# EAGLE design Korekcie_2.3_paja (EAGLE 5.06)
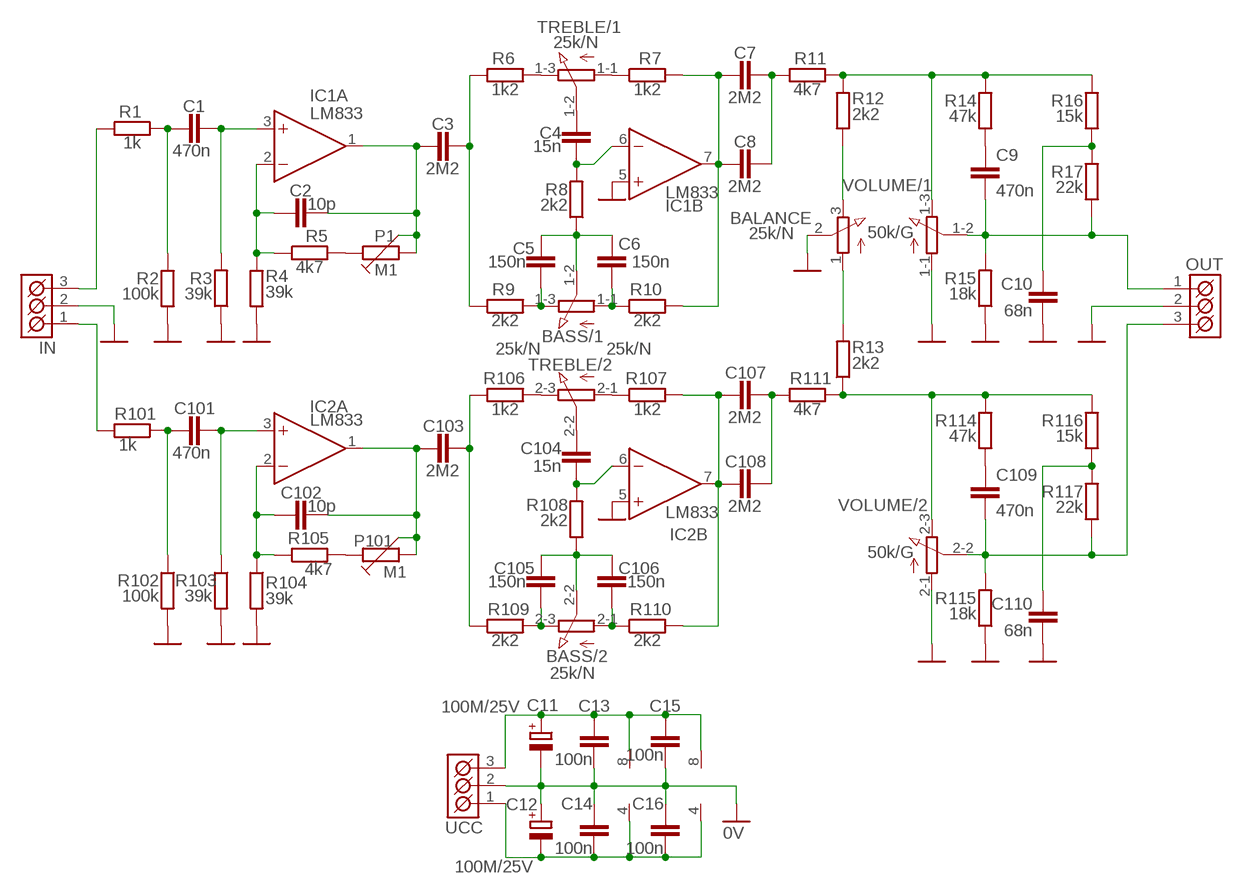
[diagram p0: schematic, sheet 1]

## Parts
BALANCE  25k/N  3RP/1610N  [3RP/1610N]
BASS  25k/N  3RP/1610G  [3RP/1610G]
C1  470n  C-EU050-055X075  [C050-055X075]
C2  10p  C-EU025-024X044  [C025-024X044]
C3  2M2  C-EU050-055X075  [C050-055X075]
C4  15n  C-EU050-025X075  [C050-025X075]
C5  150n  C-EU050-025X075  [C050-025X075]
C6  150n  C-EU050-025X075  [C050-025X075]
C7  2M2  C-EU050-055X075  [C050-055X075]
C8  2M2  C-EU050-055X075  [C050-055X075]
C9  470n  C-EU050-055X075  [C050-055X075]
C10  68n  C-EU050-025X075  [C050-025X075]
C11  100M/25V  CPOL-EUE3.5-8  [E3,5-8]
C12  100M/25V  CPOL-EUE3.5-8  [E3,5-8]
C13  100n  C-EU050-025X075  [C050-025X075]
C14  100n  C-EU050-025X075  [C050-025X075]
C15  100n  C-EU050-025X075  [C050-025X075]
C16  100n  C-EU050-025X075  [C050-025X075]
C101  470n  C-EU050-055X075  [C050-055X075]
C102  10p  C-EU025-024X044  [C025-024X044]
C103  2M2  C-EU050-055X075  [C050-055X075]
C104  15n  C-EU050-025X075  [C050-025X075]
C105  150n  C-EU050-025X075  [C050-025X075]
C106  150n  C-EU050-025X075  [C050-025X075]
C107  2M2  C-EU050-055X075  [C050-055X075]
C108  2M2  C-EU050-055X075  [C050-055X075]
C109  470n  C-EU050-055X075  [C050-055X075]
C110  68n  C-EU050-025X075  [C050-025X075]
IC1  LM833  [DIL-08]
IC2  LM833  [DIL-08]
IN  ARK500/3  [ARK500/3]
OUT  ARK500/3  [ARK500/3]
P1  M1  TRIMRPT10V  [PT10V]
P101  M1  TRIMRPT10V  [PT10V]
R1  1k  R-EU_0204/7  [0204/7]
R2  100k  R-EU_0204/7  [0204/7]
R3  39k  R-EU_0204/7  [0204/7]
R4  39k  R-EU_0204/7  [0204/7]
R5  4k7  R-EU_0204/7  [0204/7]
R6  1k2  R-EU_0204/7  [0204/7]
R7  1k2  R-EU_0207/12  [0207/12]
R8  2k2  R-EU_0204/7  [0204/7]
R9  2k2  R-EU_0204/7  [0204/7]
R10  2k2  R-EU_0204/7  [0204/7]
R11  4k7  R-EU_0204/7  [0204/7]
R12  2k2  R-EU_0204/7  [0204/7]
R13  2k2  R-EU_0204/7  [0204/7]
R14  47k  R-EU_0204/7  [0204/7]
R15  18k  R-EU_0204/7  [0204/7]
R16  15k  R-EU_0204/7  [0204/7]
R17  22k  R-EU_0204/7  [0204/7]
R101  1k  R-EU_0204/7  [0204/7]
R102  100k  R-EU_0204/7  [0204/7]
R103  39k  R-EU_0204/7  [0204/7]
R104  39k  R-EU_0204/7  [0204/7]
R105  4k7  R-EU_0204/7  [0204/7]
R106  1k2  R-EU_0204/7  [0204/7]
R107  1k2  R-EU_0207/10  [0207/10]
R108  2k2  R-EU_0204/7  [0204/7]
R109  2k2  R-EU_0204/7  [0204/7]
R110  2k2  R-EU_0204/7  [0204/7]
R111  4k7  R-EU_0204/7  [0204/7]
R114  47k  R-EU_0204/7  [0204/7]
R115  18k  R-EU_0204/7  [0204/7]
R116  15k  R-EU_0204/7  [0204/7]
R117  22k  R-EU_0204/7  [0204/7]
TREBLE  25k/N  3RP/1610G  [3RP/1610G]
UCC  ARK500/3  [ARK500/3]
VOLUME  50k/G  3RP/1610G  [3RP/1610G]

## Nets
0V: BALANCE.2(S) C10.1 C11.- C12.+ C13.1 C14.2 C15.1 C16.2 C110.1 IC1.5(B:+IN) IC2.5(B:+IN) IN.2(K2) OUT.2(K2) R2.2 R3.1 R4.2 R15.1 R102.2 R103.2 R104.2 R115.1 UCC.2(K2) VOLUME.1-1(/1:A) VOLUME.2-1(/2:A)
+VCC: C11.+ C13.2 C15.2 IC1.8(P:V+) IC2.8(P:V+) UCC.3(K3)
-VCC: C12.- C14.1 C16.1 IC1.4(P:V-) IC2.4(P:V-) UCC.1(K1)
N$1: C1.2 IC1.3(A:+IN) R3.2
N$2: C2.1 IC1.2(A:-IN) R4.1 R5.1
N$3: P1.1 R5.2
N$4: C2.2 C3.1 IC1.1(A:OUT) P1.2 P1.3
N$5: C1.1 R1.1 R2.1
N$6: C3.2 R6.1 R9.1
N$7: C101.2 IC2.3(A:+IN) R103.1
N$8: C101.1 R101.1 R102.1
N$9: C102.1 IC2.2(A:-IN) R104.1 R105.1
N$10: P101.1 R105.2
N$11: C102.2 C103.1 IC2.1(A:OUT) P101.2 P101.3
N$12: C103.2 R106.1 R109.1
N$13: IN.3(K3) R1.2
N$14: IN.1(K1) R101.2
N$15: BASS.2-3(/2:E) C105.2 R109.2
N$16: C4.2 TREBLE.1-2(/1:S)
N$17: C4.1 IC1.6(B:-IN) R8.2
N$18: BASS.2-1(/2:A) C106.2 R110.1
N$19: BASS.1-3(/1:E) C5.2 R9.2
N$20: BASS.1-2(/1:S) C5.1 C6.2 R8.1
N$21: BASS.1-1(/1:A) C6.1 R10.1
N$22: C7.1 C8.1 IC1.7(B:OUT) R7.2 R10.2
N$23: C7.2 C8.2 R11.1
N$24: R107.1 TREBLE.2-1(/2:A)
N$25: R106.2 TREBLE.2-3(/2:E)
N$26: C104.2 TREBLE.2-2(/2:S)
N$27: C104.1 IC2.6(B:-IN) R108.2
N$28: C107.2 C108.2 IC2.7(B:OUT) R107.2 R110.2
N$29: BASS.2-2(/2:S) C105.1 C106.1 R108.1
N$30: R6.2 TREBLE.1-3(/1:E)
N$31: R7.1 TREBLE.1-1(/1:A)
N$32: C107.1 C108.1 R111.1
N$33: C109.2 OUT.3(K3) R115.2 R117.1 VOLUME.2-2(/2:S)
N$35: BALANCE.1(A) R13.2
N$36: BALANCE.3(E) R12.1
N$37: C9.1 R14.1
N$38: C10.2 R16.1 R17.2
N$39: R11.2 R12.2 R14.2 R16.2 VOLUME.1-3(/1:E)
N$40: C9.2 OUT.1(K1) R15.2 R17.1 VOLUME.1-2(/1:S)
N$41: C110.2 R116.1 R117.2
N$42: C109.1 R114.1
N$43: R13.1 R111.2 R114.2 R116.2 VOLUME.2-3(/2:E)

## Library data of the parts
BALANCE = pot:3RP/1610N: 16mm Potentiometer one level Source: http://www.alphapotentiometers.net/html/16mm_pot_2.html
BASS TREBLE VOLUME = 0 nalimko:3RP/1610G: 16mm Potentiometer two level Source: http://www.alphapotentiometers.net/html/16mm_pot_2.html
C1-C10 C13-C16 C101-C110 = rcl:C-EU: CAPACITOR, European symbol
C11 C12 = rcl:CPOL-EU: POLARIZED CAPACITOR, European symbol
IC1 IC2 = #_GM99:LM833
IN OUT UCC = #PaJa_konektory:ARK500/3: Svorkovnice - roztec 5mm - trojita
P1 P101 = #PaJa_22:TRIMR: Trimr
R1-R17 R101-R111 R114-R117 = rcl:R-EU_: RESISTOR, European symbol

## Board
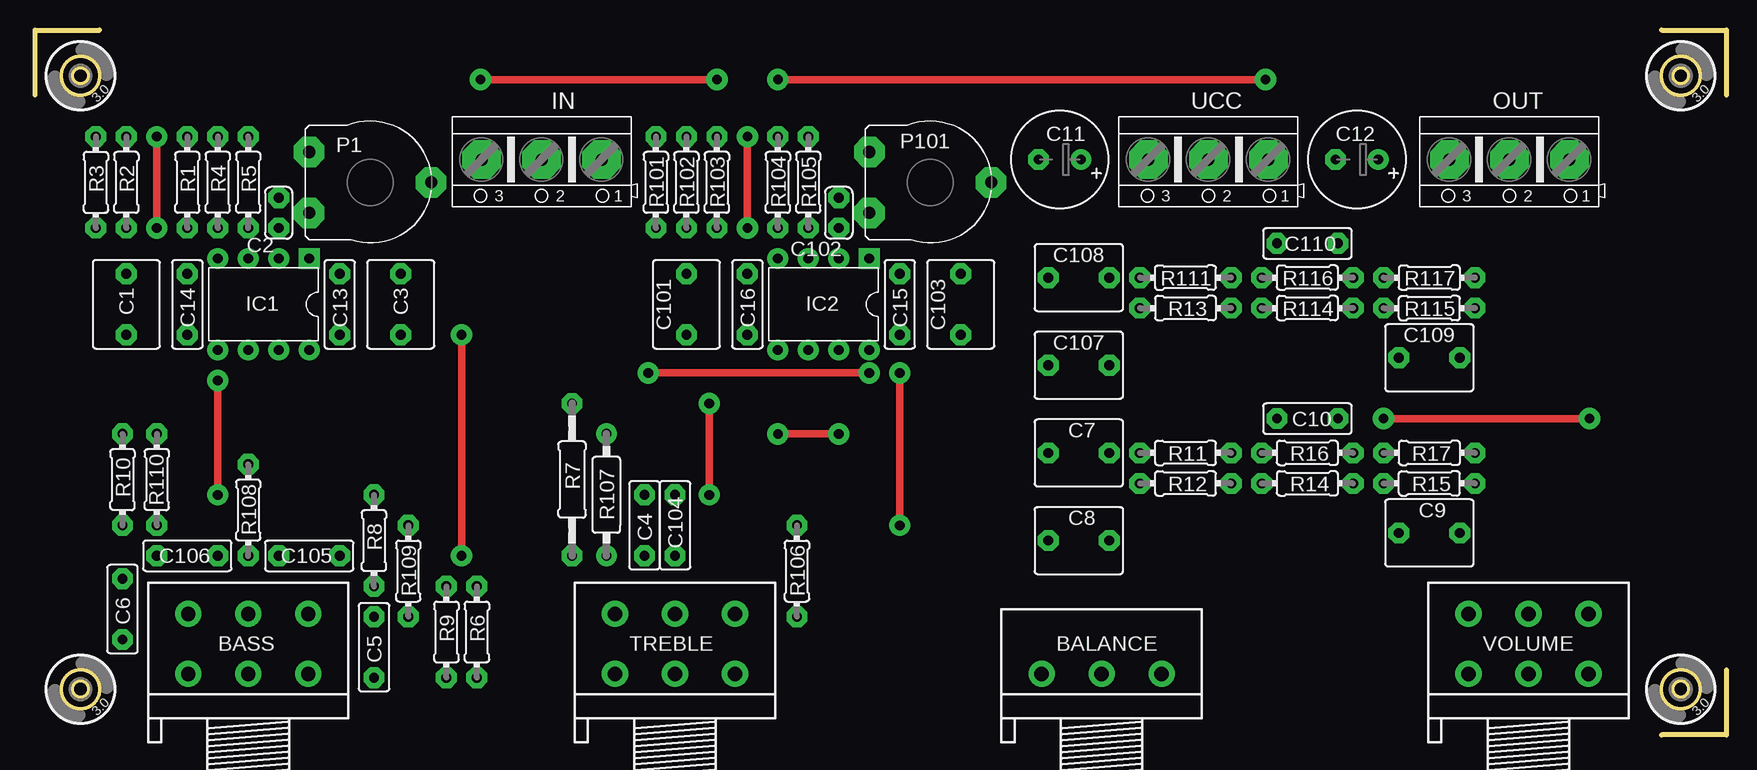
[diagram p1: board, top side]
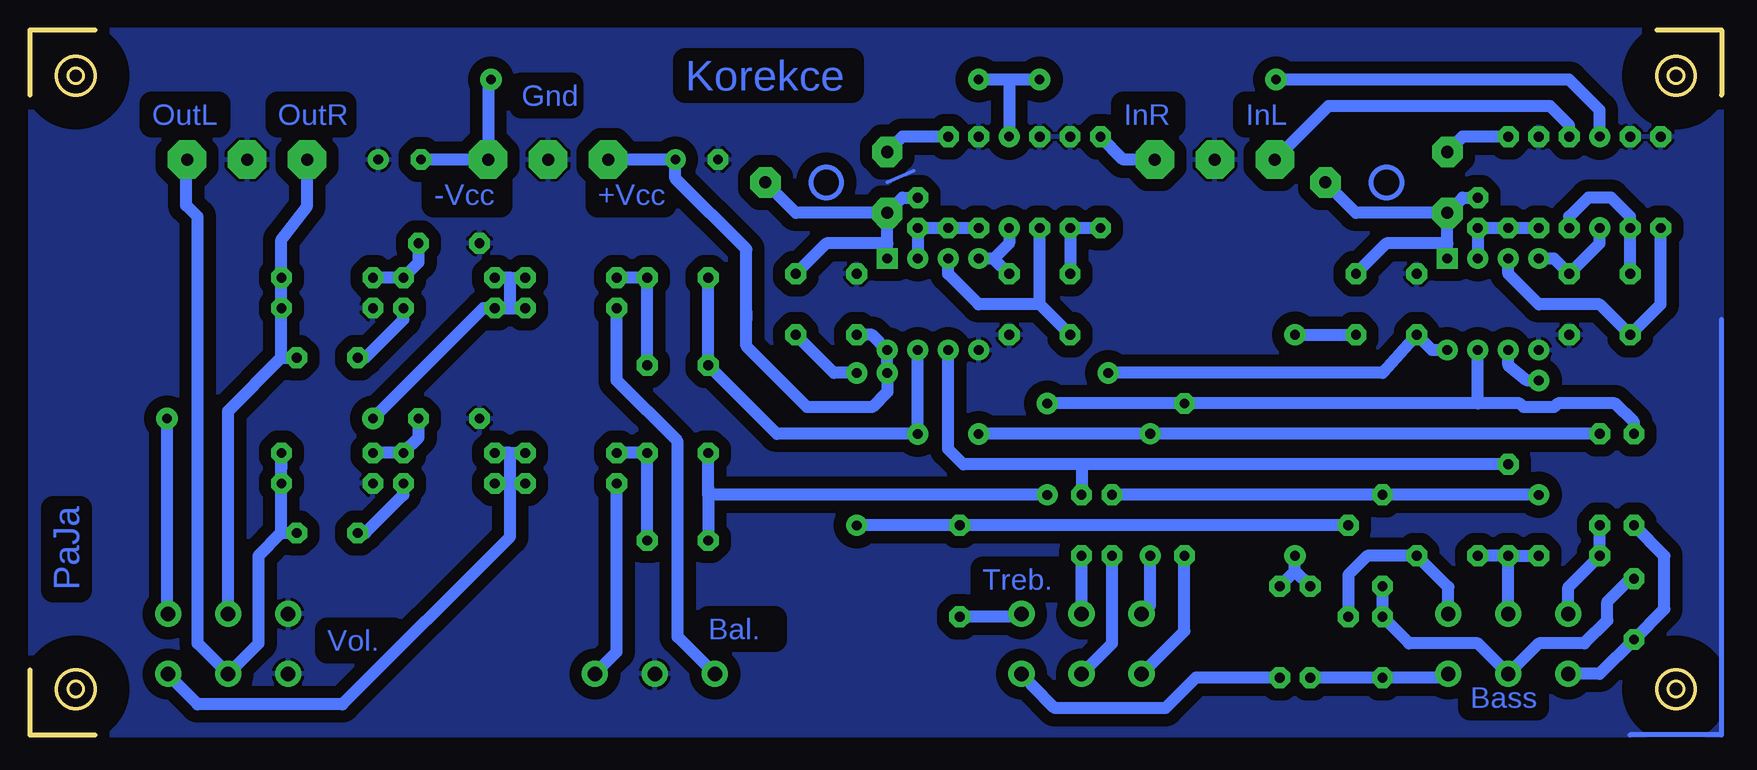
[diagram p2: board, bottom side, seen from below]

Size 140.97 x 58.74 mm. Coordinates in mm from the lower left corner, seen from the top.
Outline: 0,53.34 0,58.74 5.4,58.74
Outline: 135.57,58.74 140.97,58.74 140.97,53.34
Outline: 140.97,5.4 140.97,0 135.57,0
Copper layers (1*16): Top 0.035mm / dielectric 1.5mm / Bottom 0.035mm
Design rules "default *": minimum track width 10mil, minimum drill 24mil, track to track 8mil, track to pad 8mil, pad to pad 8mil, via to via 8mil, smd to smd 8mil, copper to edge 40mil, drill to drill 8mil, minimum pad ring 18mil, minimum via ring 8mil, stop-mask expansion 4mil, vias tented up to drill 0mil, thermal gap 10mil

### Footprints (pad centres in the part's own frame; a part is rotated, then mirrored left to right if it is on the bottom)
3RP/1610N = drill 1.2 pad 2.184 round: 1 -5,0; 2 0,0; 3 5,0
3RP/1610G = drill 1.2 pad 2.184 round: 1-1 -5,0; 1-2 0,0; 1-3 5,0; 2-1 -5,5; 2-2 0,5; 2-3 5,5
C050-055X075 = drill 0.813 octagon: 1 -2.54,0; 2 2.54,0
C025-024X044 = drill 0.813 octagon: 1 -1.27,0; 2 1.27,0
C050-025X075 = drill 0.813 octagon: 1 -2.54,0; 2 2.54,0
E3,5-8 = drill 0.813 pad 1.6 round: + -1.778,0 | drill 0.813 pad 1.6 octagon: - 1.778,0
HOLE_3,0 = hole 3.2: 0,0
DIL-08 = drill 0.813 pad 1.397 square: 1 -3.81,-3.81 | drill 0.813 pad 1.397 round: 2 -1.27,-3.81; 3 1.27,-3.81; 4 3.81,-3.81; 5 3.81,3.81; 6 1.27,3.81; 7 -1.27,3.81; 8 -3.81,3.81
ARK500/3 = drill 1 pad 3.2 octagon: 1 -5,0; 2 0,0; 3 5,0
PT10V = drill 1.016 pad 2.54 octagon: 1 -2.54,-5.08; 2 0,5.08; 3 2.54,-5.08
0204/7 = drill 0.813 octagon: 1 -3.81,0; 2 3.81,0
0207/12 = drill 0.813 octagon: 1 -6.35,0; 2 6.35,0
0207/10 = drill 0.813 round: 1 -5.08,0; 2 5.08,0

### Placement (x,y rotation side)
BALANCE  88.9,5.08 0 top
BASS  17.78,5.08 0 top
C1  7.62,35.88 270 top
C2  20.32,43.5 90 top
C3  30.48,35.88 270 top
C4  50.8,17.46 270 top
C5  28.26,7.3 270 top
C6  7.3,10.48 90 top
C7  87,23.5 0 top
C8  87,16.19 0 top
C9  116.2,16.83 0 top
C10  106.05,26.35 0 top
C11  85.41,47.94 180 top
C12  110.17,47.94 180 top
C13  25.4,35.88 270 top
C14  12.7,35.88 270 top
C15  72.07,35.88 270 top
C16  59.37,35.88 270 top
C101  54.29,35.88 270 top
C102  66.99,43.5 90 top
C103  77.15,35.88 270 top
C104  53.34,17.46 270 top
C105  22.86,14.92 0 top
C106  12.7,14.92 180 top
C107  87,30.8 180 top
C108  87,38.1 180 top
C109  116.2,31.43 0 top
C110  106.05,40.96 0 top
E$1  [HOLE_3,0]  3.81,3.81 0 top
E$2  [HOLE_3,0]  3.81,54.93 0 top
E$3  [HOLE_3,0]  137.16,3.81 0 top
E$4  [HOLE_3,0]  137.16,54.93 0 top
IC1  19.05,35.88 180 top
IC2  65.72,35.88 180 top
IN  42.23,47.94 180 top
OUT  122.87,47.94 180 top
P1  27.94,46.04 270 top
P101  74.61,46.04 270 top
R1  12.7,46.04 90 top
R2  7.62,46.04 90 top
R3  5.08,46.04 270 top
R4  15.24,46.04 90 top
R5  17.78,46.04 90 top
R6  36.83,8.57 270 top
R7  44.77,21.27 90 top
R8  28.26,16.19 90 top
R9  34.29,8.57 270 top
R10  7.3,21.27 90 top
R11  95.89,23.5 0 top
R12  95.89,20.95 0 top
R13  95.89,35.56 180 top
R14  106.05,20.95 180 top
R15  116.2,20.95 0 top
R16  106.05,23.5 180 top
R17  116.2,23.5 180 top
R101  51.75,46.04 90 top
R102  54.29,46.04 90 top
R103  56.83,46.04 90 top
R104  61.91,46.04 90 top
R105  64.45,46.04 90 top
R106  63.5,13.65 270 top
R107  47.62,20 90 top
R108  17.78,18.73 90 top
R109  31.11,13.65 270 top
R110  10.16,21.27 90 top
R111  95.89,38.1 0 top
R114  106.05,35.56 180 top
R115  116.2,35.56 0 top
R116  106.05,38.1 180 top
R117  116.2,38.1 180 top
TREBLE  53.34,5.08 0 top
UCC  97.79,47.94 180 top
VOLUME  124.46,5.08 0 top

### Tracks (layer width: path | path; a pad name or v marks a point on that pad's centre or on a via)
0V
  Bottom 0.305: 67.31,46.99 69.53,46.04
  Bottom 0.406: 0,34.61 0,0 7.62,0
  pour Bottom (isolate 1.016): 0,58.74 140.97,58.74 140.97,0 0,0
+VCC  (via drill 0.8 pad 1.78)
  Top 0.61: v51.12,30.16 v69.53,30.16
  Bottom 1.016: IC1.8 24.13,32.07 C13.2 28.26,30.16 v51.12,30.16 | 81.28,35.24 81.28,34.61 | 81.28,35.24 81.28,40.45 87.19,46.35 C11.+ UCC.3 | C15.2 70.8,33.34 IC2.8 v69.53,30.16 69.53,28.57 70.8,27.3 76.2,27.3 81.28,32.38 81.28,35.24
-VCC  (via drill 0.8 pad 1.78)
  Top 0.61: v10.16,42.23 v10.16,49.85 | v37.15,54.61 v56.83,54.61 | v61.91,54.61 v102.55,54.61 | v59.37,49.85 v59.37,42.23
  Bottom 1.016: 59.37,54.61 v61.91,54.61 | 59.37,54.61 v59.37,49.85 | v56.83,54.61 59.37,54.61 | v102.55,54.61 102.79,54.53 UCC.1 C12.- | v59.37,42.23 59.37,40.96 60.64,39.69 | 60.64,39.69 C16.1 | 60.64,39.69 IC2.4 | v10.16,49.85 10.16,52.07 12.7,54.61 v37.15,54.61 | v10.16,42.23 10.16,40.96 C14.1 13.97,39.69 IC1.4
N$1
  Bottom 1.016: IC1.3 17.78,38.42 15.24,35.88 10.16,35.88 C1.2 5.08,35.88 R3.2
N$2
  Bottom 1.016: R4.1 R5.1 C2.1 IC1.2
N$3
  Bottom 1.016: P1.1 21.59,49.85 R5.2
N$4
  Bottom 1.016: 22.86,40.96 P1.3 | IC1.1 22.86,40.96 | P1.3 21.59,44.77 C2.2 | C3.1 27.94,40.96 22.86,40.96 | P1.2 30.48,43.5 P1.3
N$5
  Bottom 1.016: C1.1 R2.1 7.62,43.18 9.21,44.77 11.11,44.77 12.7,43.18 R1.1
N$6  (via drill 0.8 pad 1.78)
  Top 0.61: v35.56,14.92 v35.56,33.34
  Bottom 1.016: v35.56,33.34 C3.2 | R9.1 35.56,13.65 | 35.56,13.65 R6.1 | 35.56,13.65 v35.56,14.92
N$7
  Bottom 1.016: C101.2 56.83,35.88 | 56.83,35.88 61.91,35.88 64.45,38.42 IC2.3 | 56.83,35.88 R103.1
N$8
  Bottom 1.016: R101.1 R102.1 C101.1
N$9
  Bottom 1.016: R104.1 R105.1 C102.1 IC2.2
N$10
  Bottom 1.016: P101.1 68.26,49.85 R105.2
N$11
  Bottom 1.016: P101.3 68.26,44.77 C102.2 | IC2.1 69.53,40.96 | 69.53,40.96 P101.3 | C103.1 74.61,40.96 69.53,40.96 | P101.2 77.15,43.5 P101.3
N$12  (via drill 0.8 pad 1.78)
  Top 0.61: v72.07,17.46 v72.07,30.16
  Bottom 1.016: v72.07,17.46 R106.1 R109.1 | C103.2 73.98,30.16 v72.07,30.16
N$13
  Bottom 1.016: IN.3 32.78,52.39 14.29,52.39 12.7,50.8 R1.2
N$14
  Bottom 1.016: IN.1 49.85,47.94 R101.2
N$15
  Bottom 1.016: R109.2 31.11,13.34 29.53,14.92 C105.2 22.78,12.3 BASS.2-3
N$16
  Bottom 1.016: TREBLE.1-2 50.8,7.62 C4.2
N$17  (via drill 0.8 pad 1.78)
  Top 0.61: v15.24,20 v15.24,29.53
  Bottom 1.016: v15.24,29.53 16.19,29.53 17.78,30.8 IC1.6 | C4.1 R8.2 v15.24,20
N$18
  Bottom 1.016: R110.1 C106.2 12.78,12.3 BASS.2-1
N$19
  Bottom 1.016: R9.2 C5.2 23.1,4.76 BASS.1-3
N$20
  Bottom 1.016: C6.2 7.62,13.02 9.53,11.11 9.53,9.53 11.43,7.62 15.24,7.62 BASS.1-2 20.32,7.62 26.04,7.62 C5.1 R8.1
N$21
  Bottom 1.016: BASS.1-1 10.16,5.08 C6.1 4.76,10.48 4.76,14.92 R10.1
N$22  (via drill 0.8 pad 1.78)
  Top 0.61: v56.2,27.62 v56.2,20
  Bottom 1.016: 84.45,20.64 C8.1 | 84.45,20.64 C7.1 | 20.32,27.62 IC1.7 | v56.2,27.62 R7.2 20.32,27.62 | R10.2 7.3,26.04 8.89,27.62 13.65,27.62 13.97,27.3 16.51,27.3 16.83,27.62 20.32,27.62 | v56.2,20 84.45,20 84.45,20.64
N$23
  Bottom 1.016: C8.2 C7.2 R11.1
N$24
  Bottom 1.016: R107.1 47.62,10.79 TREBLE.2-1
N$25
  Bottom 1.016: R106.2 58.58,9.84 TREBLE.2-3
N$26
  Bottom 1.016: TREBLE.2-2 C104.2
N$27
  Bottom 1.016: 53.34,22.54 C104.1 | R108.2 53.34,22.54 | IC2.6 64.45,23.81 63.18,22.54 53.34,22.54
N$28  (via drill 0.8 pad 1.78)
  Top 0.61: v61.91,25.08 v66.99,25.08
  Bottom 1.016: C108.2 C107.2 78.74,25.08 v66.99,25.08 IC2.7 | R110.2 R107.2 v61.91,25.08
N$29
  Bottom 1.016: R108.1 C106.1 | R108.1 C105.1 | BASS.2-2 R108.1
N$30
  Bottom 1.016: TREBLE.1-3 58.42,5 57.47,4.13 55.56,2.22 46.35,2.22 43.81,4.76 R6.2
N$31
  Bottom 1.016: R7.1 44.77,8.65 TREBLE.1-1
N$32
  Bottom 1.016: C107.1 C108.1 R111.1
N$33
  Bottom 1.016: OUT.3 117.87,44.05 120.02,41.27 R117.1 R115.2 120.02,31.43 | 120.02,31.43 124.46,26.99 VOLUME.2-2 | 120.02,31.43 C109.2
N$35
  Bottom 1.016: BALANCE.1 87,8.18 87,24.45 92.08,29.53 R13.2
N$36
  Bottom 1.016: R12.1 92.08,6.91 BALANCE.3
N$37
  Bottom 1.016: R14.1 109.86,20 113.03,16.83 C9.1
N$38
  Bottom 1.016: R17.2 R16.1 108.58,24.77 C10.2
N$39
  Bottom 1.016: VOLUME.1-3 129.46,5 127,2.54 114.94,2.54 100.97,16.51 100.97,20.95 | 100.97,23.5 R11.2 | 100.97,23.5 R16.2 | 100.97,20.95 100.97,23.5 | 100.97,20.95 R14.2 | 100.97,20.95 R12.2
N$40
  Bottom 1.016: 120.02,22.23 R17.1 R15.2 120.02,16.83 | OUT.1 127.95,47.86 127.95,44.13 127,43.18 127,7.62 VOLUME.1-2 121.92,7.62 121.92,14.92 120.02,16.83 | 120.02,16.83 C9.2
N$41
  Bottom 1.016: R117.2 R116.1 108.58,39.37 C110.2
N$42
  Bottom 1.016: R114.1 109.86,34.61 113.03,31.43 C109.1
N$43  (via drill 0.8 pad 1.78)
  Top 0.61: v129.54,26.35 v112.39,26.35
  Bottom 1.016: 100.97,38.1 R111.2 | 100.97,35.56 R13.1 | v129.54,26.35 129.54,10.16 VOLUME.2-3 | 100.97,35.56 100.97,38.1 | 100.97,38.1 R116.2 | 100.97,35.56 R114.2 102.87,35.56 103.19,35.56 v112.39,26.35
(copper drawn outside any net)
  shapes: Bottom circle x2

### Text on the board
Bottom: Korekce | Gnd | InL | InR | OutR | OutL | +Vcc | -Vcc | Treb. | PaJa | Bal. | Vol. | Bass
